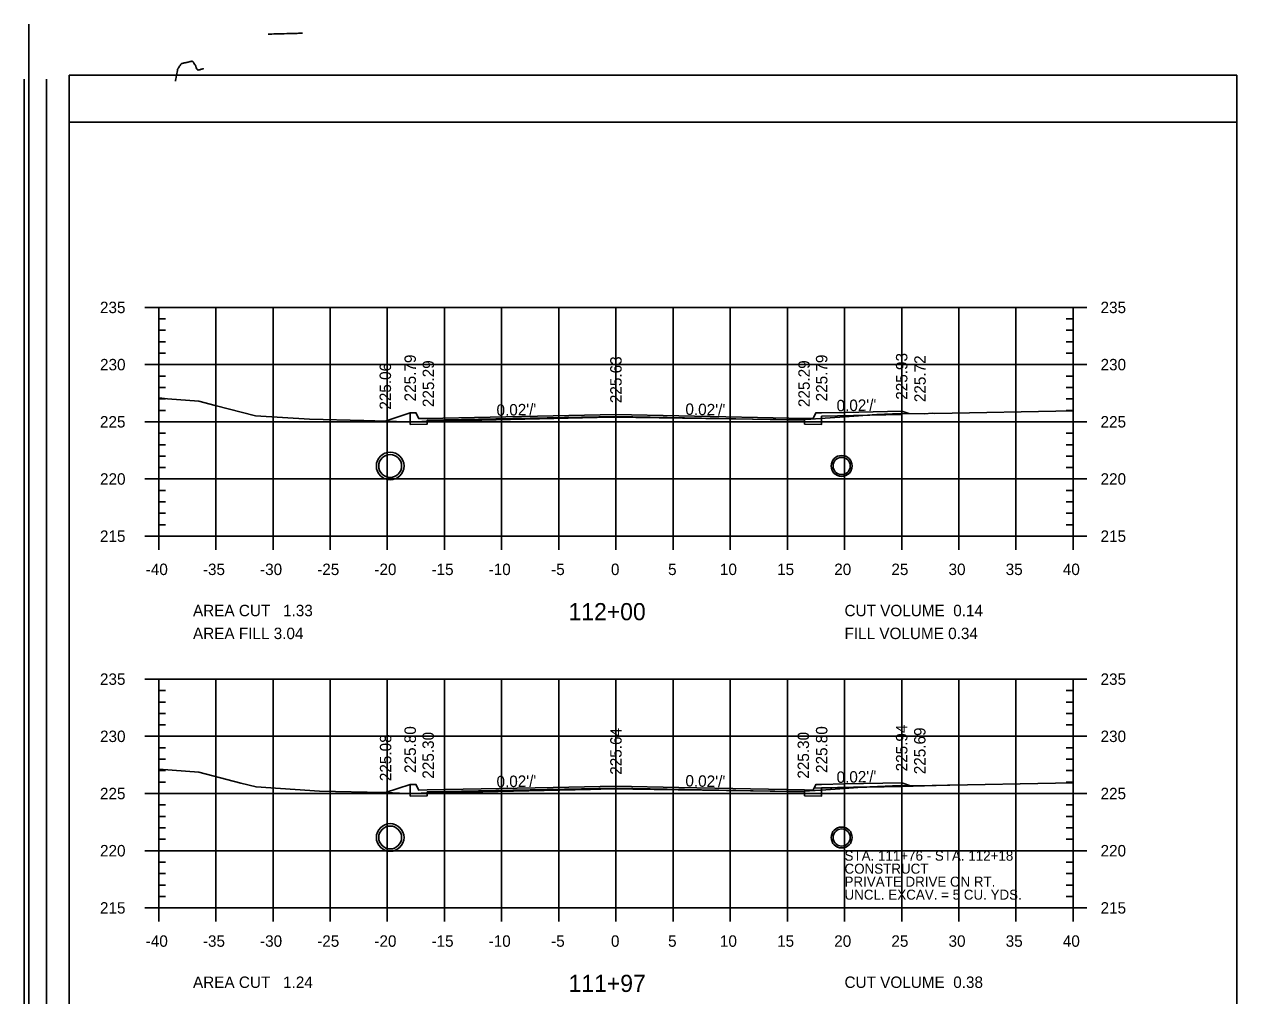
# Model space of a CAD drawing. Extents: x 1367903 to 1373764, y 376865 to 382130.
# Drawn here: x 1372830.3 to 1373042.4, y 377450.5 to 377620.4 of the extents above; entities that cross this region are included whole.
import ezdxf

# ---------------------------------------------------------------- set-up
doc = ezdxf.new("R2010")
doc.units = 0
for name, color, linetype in [('R_Axis', 7, 'Continuous'), ('R_Axis Annot', 7, 'Continuous'), ('R_Border', 7, 'Continuous'), ('R_Border PE', 7, 'Continuous'), ('R_Draft', 7, 'Continuous'), ('R_Drive', 7, 'Continuous'), ('R_Exist Surface', 7, 'Continuous'), ('R_Fin Surface', 7, 'Continuous'), ('R_Fin Surface Annot', 7, 'Continuous'), ('R_Grid', 7, 'Continuous'), ('R_Water', 7, 'Continuous')]:
    doc.layers.add(name, color=color, linetype=linetype)

msp = doc.modelspace()

# ---------------------------------------------------------------- linework, layer by layer
for points in [[(1372897.8, 377552.41), (1372897.8, 377551.74), (1372897.8, 377551.74), (1372897.8, 377550.38), (1372900.8, 377550.44), (1372900.8, 377551.11), (1372933.8, 377551.77), (1372966.8, 377551.11), (1372966.8, 377550.44), (1372969.8, 377550.38), (1372969.8, 377551.82), (1372983.8, 377552.1), (1372983.8, 377552.69)], [(1372897.8, 377487.43), (1372897.8, 377486.77), (1372897.8, 377486.77), (1372897.8, 377485.4), (1372900.8, 377485.46), (1372900.8, 377486.13), (1372933.8, 377486.79), (1372966.8, 377486.13), (1372966.8, 377485.46), (1372969.8, 377485.4), (1372969.8, 377486.85), (1372983.8, 377487.13), (1372983.8, 377487.71)]]:
    msp.add_lwpolyline(points)
at = {"layer": 'R_Axis'}
for p, q in [((1372851.4, 377570.84), (1372856.2, 377570.84)), ((1372853.8, 377530.84), (1372853.8, 377570.84)), ((1373016.2, 377570.84), (1373011.4, 377570.84)), ((1373013.8, 377530.84), (1373013.8, 377570.84)), ((1372853.8, 377568.84), (1372855, 377568.84)), ((1373013.8, 377568.84), (1373012.6, 377568.84)), ((1372853.8, 377566.84), (1372855, 377566.84)), ((1373013.8, 377566.84), (1373012.6, 377566.84)), ((1372853.8, 377564.84), (1372855, 377564.84)), ((1373013.8, 377564.84), (1373012.6, 377564.84)), ((1372853.8, 377562.84), (1372855, 377562.84)), ((1373013.8, 377562.84), (1373012.6, 377562.84)), ((1372851.4, 377560.84), (1372856.2, 377560.84)), ((1373016.2, 377560.84), (1373011.4, 377560.84)), ((1372853.8, 377558.84), (1372855, 377558.84)), ((1373013.8, 377558.84), (1373012.6, 377558.84)), ((1372853.8, 377556.84), (1372855, 377556.84)), ((1373013.8, 377556.84), (1373012.6, 377556.84)), ((1372853.8, 377554.84), (1372855, 377554.84)), ((1373013.8, 377554.84), (1373012.6, 377554.84)), ((1372853.8, 377552.84), (1372855, 377552.84)), ((1373013.8, 377552.84), (1373012.6, 377552.84)), ((1372851.4, 377550.84), (1372856.2, 377550.84)), ((1373016.2, 377550.84), (1373011.4, 377550.84)), ((1372853.8, 377548.84), (1372855, 377548.84)), ((1372853.8, 377546.84), (1372855, 377546.84)), ((1373013.8, 377548.84), (1373012.6, 377548.84)), ((1373013.8, 377546.84), (1373012.6, 377546.84)), ((1372853.8, 377544.84), (1372855, 377544.84)), ((1373013.8, 377544.84), (1373012.6, 377544.84)), ((1372853.8, 377542.84), (1372855, 377542.84)), ((1373013.8, 377542.84), (1373012.6, 377542.84)), ((1372851.4, 377540.84), (1372856.2, 377540.84)), ((1373016.2, 377540.84), (1373011.4, 377540.84)), ((1372853.8, 377538.84), (1372855, 377538.84)), ((1373013.8, 377538.84), (1373012.6, 377538.84)), ((1372853.8, 377536.84), (1372855, 377536.84)), ((1373013.8, 377536.84), (1373012.6, 377536.84)), ((1372853.8, 377534.84), (1372855, 377534.84)), ((1373013.8, 377534.84), (1373012.6, 377534.84)), ((1372853.8, 377528.44), (1372853.8, 377533.24)), ((1372853.8, 377532.84), (1372855, 377532.84)), ((1372863.8, 377528.44), (1372863.8, 377533.24)), ((1372873.8, 377528.44), (1372873.8, 377533.24)), ((1372883.8, 377528.44), (1372883.8, 377533.24)), ((1372893.8, 377528.44), (1372893.8, 377533.24)), ((1372903.8, 377528.44), (1372903.8, 377533.24)), ((1372913.8, 377528.44), (1372913.8, 377533.24)), ((1372923.8, 377528.44), (1372923.8, 377533.24)), ((1372933.8, 377528.44), (1372933.8, 377533.24)), ((1372943.8, 377528.44), (1372943.8, 377533.24)), ((1372953.8, 377528.44), (1372953.8, 377533.24)), ((1372963.8, 377528.44), (1372963.8, 377533.24)), ((1372973.8, 377528.44), (1372973.8, 377533.24)), ((1372983.8, 377528.44), (1372983.8, 377533.24)), ((1372993.8, 377528.44), (1372993.8, 377533.24)), ((1373003.8, 377528.44), (1373003.8, 377533.24)), ((1373013.8, 377532.84), (1373012.6, 377532.84)), ((1373013.8, 377528.44), (1373013.8, 377533.24)), ((1372851.4, 377530.84), (1372856.2, 377530.84)), ((1372853.8, 377530.84), (1373013.8, 377530.84)), ((1373016.2, 377530.84), (1373011.4, 377530.84)), ((1372851.4, 377505.84), (1372856.2, 377505.84)), ((1372853.8, 377465.84), (1372853.8, 377505.84)), ((1373016.2, 377505.84), (1373011.4, 377505.84)), ((1373013.8, 377465.84), (1373013.8, 377505.84)), ((1372853.8, 377503.84), (1372855, 377503.84)), ((1373013.8, 377503.84), (1373012.6, 377503.84)), ((1372853.8, 377501.84), (1372855, 377501.84)), ((1373013.8, 377501.84), (1373012.6, 377501.84)), ((1372853.8, 377499.84), (1372855, 377499.84)), ((1373013.8, 377499.84), (1373012.6, 377499.84)), ((1372853.8, 377497.84), (1372855, 377497.84)), ((1373013.8, 377497.84), (1373012.6, 377497.84)), ((1372851.4, 377495.84), (1372856.2, 377495.84)), ((1372853.8, 377493.84), (1372855, 377493.84)), ((1373016.2, 377495.84), (1373011.4, 377495.84)), ((1373013.8, 377493.84), (1373012.6, 377493.84)), ((1372853.8, 377491.84), (1372855, 377491.84)), ((1373013.8, 377491.84), (1373012.6, 377491.84)), ((1372853.8, 377489.84), (1372855, 377489.84)), ((1373013.8, 377489.84), (1373012.6, 377489.84)), ((1372853.8, 377487.84), (1372855, 377487.84)), ((1373013.8, 377487.84), (1373012.6, 377487.84)), ((1372851.4, 377485.84), (1372856.2, 377485.84)), ((1373016.2, 377485.84), (1373011.4, 377485.84)), ((1372853.8, 377483.84), (1372855, 377483.84)), ((1373013.8, 377483.84), (1373012.6, 377483.84)), ((1372853.8, 377481.84), (1372855, 377481.84)), ((1373013.8, 377481.84), (1373012.6, 377481.84)), ((1372853.8, 377479.84), (1372855, 377479.84)), ((1373013.8, 377479.84), (1373012.6, 377479.84)), ((1372853.8, 377477.84), (1372855, 377477.84)), ((1373013.8, 377477.84), (1373012.6, 377477.84)), ((1372851.4, 377475.84), (1372856.2, 377475.84)), ((1373016.2, 377475.84), (1373011.4, 377475.84)), ((1372853.8, 377473.84), (1372855, 377473.84)), ((1373013.8, 377473.84), (1373012.6, 377473.84)), ((1372853.8, 377471.84), (1372855, 377471.84)), ((1373013.8, 377471.84), (1373012.6, 377471.84)), ((1372853.8, 377469.84), (1372855, 377469.84)), ((1373013.8, 377469.84), (1373012.6, 377469.84)), ((1372853.8, 377463.44), (1372853.8, 377468.24)), ((1372853.8, 377467.84), (1372855, 377467.84)), ((1372863.8, 377463.44), (1372863.8, 377468.24)), ((1372873.8, 377463.44), (1372873.8, 377468.24)), ((1372883.8, 377463.44), (1372883.8, 377468.24)), ((1372893.8, 377463.44), (1372893.8, 377468.24)), ((1372903.8, 377463.44), (1372903.8, 377468.24)), ((1372913.8, 377463.44), (1372913.8, 377468.24)), ((1372923.8, 377463.44), (1372923.8, 377468.24)), ((1372933.8, 377463.44), (1372933.8, 377468.24)), ((1372943.8, 377463.44), (1372943.8, 377468.24)), ((1372953.8, 377463.44), (1372953.8, 377468.24)), ((1372963.8, 377463.44), (1372963.8, 377468.24)), ((1372973.8, 377463.44), (1372973.8, 377468.24)), ((1372983.8, 377463.44), (1372983.8, 377468.24)), ((1372993.8, 377463.44), (1372993.8, 377468.24)), ((1373003.8, 377463.44), (1373003.8, 377468.24)), ((1373013.8, 377467.84), (1373012.6, 377467.84)), ((1373013.8, 377463.44), (1373013.8, 377468.24)), ((1372851.4, 377465.84), (1372856.2, 377465.84)), ((1372853.8, 377465.84), (1373013.8, 377465.84)), ((1373016.2, 377465.84), (1373011.4, 377465.84))]:
    msp.add_line(p, q, dxfattribs=at)
at = {"layer": 'R_Border'}
for p, q in [((1372831.08, 377620.35), (1372831.08, 377279.12)), ((1372838.11, 377611.47), (1373042.43, 377611.47)), ((1372838.11, 377611.47), (1372838.11, 377280.59)), ((1373042.43, 377280.59), (1373042.43, 377611.47))]:
    msp.add_line(p, q, dxfattribs=at)
at = {"layer": 'R_Border PE'}
for p, q in [((1372830.27, 377610.76), (1372830.27, 377288.8)), ((1372834.19, 377610.76), (1372834.19, 377288.8)), ((1372838.11, 377603.25), (1373042.43, 377603.25)), ((1372838.11, 377288.8), (1372838.11, 377603.25)), ((1373042.43, 377603.25), (1373042.43, 377288.8))]:
    msp.add_line(p, q, dxfattribs=at)
for points in [[(1372874.97, 377618.69), (1372874.91, 377618.69), (1372874.63, 377618.68), (1372874.5, 377618.68), (1372874.43, 377618.67), (1372874.28, 377618.67), (1372873.92, 377618.66), (1372873.59, 377618.65), (1372872.96, 377618.63)], [(1372875.42, 377618.7), (1372874.97, 377618.69)], [(1372878.98, 377618.79), (1372878.63, 377618.78), (1372878.43, 377618.78), (1372878.27, 377618.77), (1372878.05, 377618.76), (1372877.89, 377618.76), (1372877.69, 377618.75), (1372877.45, 377618.75), (1372877.26, 377618.74), (1372876.97, 377618.73), (1372876.88, 377618.73), (1372876.82, 377618.73), (1372876.61, 377618.72), (1372876.5, 377618.72), (1372876.28, 377618.71), (1372876.2, 377618.72), (1372875.77, 377618.7), (1372875.53, 377618.7), (1372875.42, 377618.7)], [(1372861.66, 377612.54), (1372861.65, 377612.55), (1372861.62, 377612.55), (1372861.6, 377612.55), (1372861.58, 377612.55), (1372861.55, 377612.55), (1372861.53, 377612.55), (1372861.5, 377612.55), (1372861.36, 377612.51), (1372861.24, 377612.48), (1372860.97, 377612.41), (1372860.76, 377612.36), (1372860.73, 377612.35), (1372860.71, 377612.35), (1372860.69, 377612.34), (1372860.68, 377612.34), (1372860.67, 377612.35), (1372860.65, 377612.35), (1372860.62, 377612.36), (1372860.6, 377612.38), (1372860.58, 377612.39), (1372860.56, 377612.4), (1372860.54, 377612.42), (1372860.53, 377612.45), (1372860.51, 377612.47), (1372860.5, 377612.5), (1372860.48, 377612.55), (1372860.38, 377612.76), (1372860.27, 377613), (1372860.16, 377613.23), (1372860.15, 377613.26), (1372860.14, 377613.28), (1372860.1, 377613.34), (1372860.07, 377613.39), (1372859.95, 377613.57), (1372859.87, 377613.69), (1372859.84, 377613.74), (1372859.83, 377613.76), (1372859.81, 377613.78), (1372859.79, 377613.81), (1372859.77, 377613.83), (1372859.76, 377613.84), (1372859.74, 377613.85), (1372859.72, 377613.87), (1372859.71, 377613.87), (1372859.67, 377613.88), (1372859.65, 377613.88), (1372859.63, 377613.88), (1372859.59, 377613.88), (1372859.49, 377613.86), (1372859.32, 377613.82), (1372859.12, 377613.77), (1372858.98, 377613.74), (1372858.87, 377613.72), (1372858.73, 377613.69), (1372858.62, 377613.66), (1372858.44, 377613.63), (1372858.22, 377613.58), (1372858.17, 377613.57), (1372858.05, 377613.54), (1372857.93, 377613.52), (1372857.89, 377613.51), (1372857.86, 377613.5), (1372857.84, 377613.5), (1372857.83, 377613.49), (1372857.82, 377613.49), (1372857.8, 377613.47), (1372857.77, 377613.46), (1372857.75, 377613.44), (1372857.73, 377613.42), (1372857.7, 377613.39), (1372857.67, 377613.35), (1372857.64, 377613.31), (1372857.61, 377613.26), (1372857.54, 377613.16), (1372857.45, 377613.02), (1372857.37, 377612.89), (1372857.27, 377612.75), (1372857.22, 377612.67), (1372857.19, 377612.62), (1372857.15, 377612.55), (1372857.14, 377612.54), (1372857.13, 377612.52), (1372857.12, 377612.5), (1372857.11, 377612.48), (1372857.11, 377612.46), (1372857.1, 377612.44), (1372857.09, 377612.42), (1372857.09, 377612.39), (1372857.08, 377612.37), (1372857.08, 377612.35), (1372857.08, 377612.33), (1372857.06, 377612.24), (1372857.02, 377612), (1372856.97, 377611.76), (1372856.95, 377611.65), (1372856.87, 377611.18), (1372856.84, 377611.04), (1372856.8, 377610.84), (1372856.75, 377610.54), (1372856.72, 377610.39)]]:
    msp.add_lwpolyline(points, dxfattribs=at)
at = {"layer": 'R_Drive'}
for q in [(1372968.47, 377486.77), (1372993.8, 377487.34)]:
    msp.add_line((1372983.8, 377487.08), q, dxfattribs=at)
at = {"layer": 'R_Exist Surface'}
for points in [[(1372853.8, 377555.01), (1372855.33, 377554.87), (1372860.84, 377554.43), (1372863.67, 377553.69), (1372870.73, 377551.9), (1372880.19, 377551.29), (1372889.7, 377551.08), (1372893.58, 377550.95), (1372893.93, 377550.94), (1372896.92, 377550.83), (1372902.73, 377550.97), (1372933.04, 377551.62), (1372933.21, 377551.62), (1372965.87, 377551.18), (1372967.93, 377551.31), (1372973.77, 377551.71), (1372979.43, 377552.12), (1372983.54, 377552.28), (1372987.71, 377552.25), (1372989.19, 377552.34), (1372989.62, 377552.29), (1373013.8, 377552.73)], [(1372853.8, 377490.12), (1372860.84, 377489.57), (1372868.15, 377487.66), (1372870.85, 377486.98), (1372881.94, 377486.26), (1372893.1, 377486.01), (1372893.43, 377486), (1372893.46, 377486), (1372895.91, 377485.91), (1372896.54, 377485.87), (1372896.9, 377485.87), (1372897.03, 377485.87), (1372929.35, 377486.55), (1372933.05, 377486.65), (1372940.51, 377486.55), (1372965.8, 377486.22), (1372970.55, 377486.5), (1372973.8, 377486.73), (1372976.95, 377486.95), (1372983.55, 377487.22), (1372987.32, 377487.19), (1372989.16, 377487.26), (1373013.8, 377487.71)]]:
    msp.add_lwpolyline(points, dxfattribs=at)
at = {"layer": 'R_Fin Surface'}
for points in [[(1372893.45, 377550.96), (1372897.8, 377552.41), (1372898.8, 377552.41), (1372899.3, 377551.41), (1372900.8, 377551.44), (1372922.8, 377551.88), (1372933.8, 377552.1), (1372944.8, 377551.88), (1372966.8, 377551.44), (1372968.3, 377551.41), (1372968.8, 377552.41), (1372969.8, 377552.41), (1372973.8, 377552.49), (1372983.8, 377552.69), (1372985.05, 377552.27)], [(1372893.5, 377486), (1372897.8, 377487.43), (1372898.8, 377487.43), (1372899.3, 377486.43), (1372900.8, 377486.46), (1372922.8, 377486.9), (1372933.8, 377487.12), (1372944.8, 377486.9), (1372966.8, 377486.46), (1372968.3, 377486.43), (1372968.8, 377487.43), (1372969.8, 377487.43), (1372973.8, 377487.51), (1372983.8, 377487.71), (1372985.32, 377487.21)]]:
    msp.add_lwpolyline(points, dxfattribs=at)
at = {"layer": 'R_Grid'}
for p, q in [((1372853.8, 377570.84), (1373013.8, 377570.84)), ((1372853.8, 377530.84), (1372853.8, 377570.84)), ((1372863.8, 377530.84), (1372863.8, 377570.84)), ((1372873.8, 377530.84), (1372873.8, 377570.84)), ((1372883.8, 377530.84), (1372883.8, 377570.84)), ((1372893.8, 377530.84), (1372893.8, 377570.84)), ((1372903.8, 377530.84), (1372903.8, 377570.84)), ((1372913.8, 377530.84), (1372913.8, 377570.84)), ((1372923.8, 377530.84), (1372923.8, 377570.84)), ((1372933.8, 377530.84), (1372933.8, 377570.84)), ((1372943.8, 377530.84), (1372943.8, 377570.84)), ((1372953.8, 377530.84), (1372953.8, 377570.84)), ((1372963.8, 377530.84), (1372963.8, 377570.84)), ((1372973.8, 377530.84), (1372973.8, 377570.84)), ((1372983.8, 377530.84), (1372983.8, 377570.84)), ((1372993.8, 377530.84), (1372993.8, 377570.84)), ((1373003.8, 377530.84), (1373003.8, 377570.84)), ((1373013.8, 377530.84), (1373013.8, 377570.84)), ((1372853.8, 377560.84), (1373013.8, 377560.84)), ((1372853.8, 377550.84), (1373013.8, 377550.84)), ((1372853.8, 377540.84), (1373013.8, 377540.84)), ((1372853.8, 377530.84), (1373013.8, 377530.84)), ((1372853.8, 377505.84), (1373013.8, 377505.84)), ((1372853.8, 377465.84), (1372853.8, 377505.84)), ((1372863.8, 377465.84), (1372863.8, 377505.84)), ((1372873.8, 377465.84), (1372873.8, 377505.84)), ((1372883.8, 377465.84), (1372883.8, 377505.84)), ((1372893.8, 377465.84), (1372893.8, 377505.84)), ((1372903.8, 377465.84), (1372903.8, 377505.84)), ((1372913.8, 377465.84), (1372913.8, 377505.84)), ((1372923.8, 377465.84), (1372923.8, 377505.84)), ((1372933.8, 377465.84), (1372933.8, 377505.84)), ((1372943.8, 377465.84), (1372943.8, 377505.84)), ((1372953.8, 377465.84), (1372953.8, 377505.84)), ((1372963.8, 377465.84), (1372963.8, 377505.84)), ((1372973.8, 377465.84), (1372973.8, 377505.84)), ((1372983.8, 377465.84), (1372983.8, 377505.84)), ((1372993.8, 377465.84), (1372993.8, 377505.84)), ((1373003.8, 377465.84), (1373003.8, 377505.84)), ((1373013.8, 377465.84), (1373013.8, 377505.84)), ((1372853.8, 377495.84), (1373013.8, 377495.84)), ((1372853.8, 377485.84), (1373013.8, 377485.84)), ((1372853.8, 377475.84), (1373013.8, 377475.84)), ((1372853.8, 377465.84), (1373013.8, 377465.84))]:
    msp.add_line(p, q, dxfattribs=at)
at = {"layer": 'R_Water'}
for p, q in [((1372894.3, 377545.56), (1372894.3, 377545.51)), ((1372894.3, 377545.14), (1372894.3, 377545.09)), ((1372973.3, 377544.97), (1372973.3, 377544.93)), ((1372973.3, 377544.64), (1372973.3, 377544.59)), ((1372894.3, 377541.14), (1372894.3, 377541.09)), ((1372894.3, 377540.72), (1372894.3, 377540.67)), ((1372973.3, 377541.64), (1372973.3, 377541.59)), ((1372973.3, 377541.31), (1372973.3, 377541.26)), ((1372894.3, 377480.59), (1372894.3, 377480.54)), ((1372894.3, 377480.18), (1372894.3, 377480.13)), ((1372973.3, 377480.01), (1372973.3, 377479.96)), ((1372973.3, 377479.68), (1372973.3, 377479.63)), ((1372894.3, 377476.18), (1372894.3, 377476.13)), ((1372894.3, 377475.76), (1372894.3, 377475.71)), ((1372973.3, 377476.68), (1372973.3, 377476.63)), ((1372973.3, 377476.34), (1372973.3, 377476.3))]:
    msp.add_line(p, q, dxfattribs=at)
for centre, radius in [((1372894.3, 377543.11), 2.42), ((1372894.3, 377543.11), 2), ((1372973.3, 377543.12), 1.83), ((1372973.3, 377543.12), 1.5), ((1372894.3, 377478.15), 2.42), ((1372894.3, 377478.15), 2), ((1372973.3, 377478.15), 1.83), ((1372973.3, 377478.15), 1.5)]:
    msp.add_circle(centre, radius, dxfattribs=at)

# ---------------------------------------------------------------- texts
at = {"layer": 'R_Axis Annot'}
for s, height, p in [('235', 2, (1372843.52, 377569.84)), ('235', 2, (1373018.6, 377569.84)), ('230', 2, (1372843.53, 377559.84)), ('230', 2, (1373018.6, 377559.84)), ('225', 2, (1372843.52, 377549.84)), ('225', 2, (1373018.6, 377549.84)), ('220', 2, (1372843.53, 377539.84)), ('220', 2, (1373018.6, 377539.84)), ('215', 2, (1372843.52, 377529.84)), ('215', 2, (1373018.6, 377529.84)), ('-40', 2, (1372851.53, 377524.04)), ('-35', 2, (1372861.53, 377524.04)), ('-30', 2, (1372871.53, 377524.04)), ('-25', 2, (1372881.53, 377524.04)), ('-20', 2, (1372891.53, 377524.04)), ('-15', 2, (1372901.53, 377524.04)), ('-10', 2, (1372911.53, 377524.04)), ('-5', 2, (1372922.46, 377524.04)), ('0', 2, (1372932.93, 377524.04)), ('5', 2, (1372942.93, 377524.04)), ('10', 2, (1372952, 377524.04)), ('15', 2, (1372962, 377524.04)), ('20', 2, (1372972, 377524.04)), ('25', 2, (1372982, 377524.04)), ('30', 2, (1372992, 377524.04)), ('35', 2, (1373002, 377524.04)), ('40', 2, (1373012, 377524.04)), ('AREA CUT   1.33', 2, (1372859.8, 377516.84)), ('112+00', 3, (1372925.51, 377516.14)), ('CUT VOLUME  0.14', 2, (1372973.8, 377516.84)), ('AREA FILL 3.04', 2, (1372859.8, 377512.84)), ('FILL VOLUME 0.34', 2, (1372973.8, 377512.84)), ('235', 2, (1372843.52, 377504.84)), ('235', 2, (1373018.6, 377504.84)), ('230', 2, (1372843.53, 377494.84)), ('230', 2, (1373018.6, 377494.84)), ('225', 2, (1372843.52, 377484.84)), ('225', 2, (1373018.6, 377484.84)), ('220', 2, (1372843.53, 377474.84)), ('220', 2, (1373018.6, 377474.84)), ('215', 2, (1372843.52, 377464.84)), ('215', 2, (1373018.6, 377464.84)), ('-40', 2, (1372851.53, 377459.04)), ('-35', 2, (1372861.53, 377459.04)), ('-30', 2, (1372871.53, 377459.04)), ('-25', 2, (1372881.53, 377459.04)), ('-20', 2, (1372891.53, 377459.04)), ('-15', 2, (1372901.53, 377459.04)), ('-10', 2, (1372911.53, 377459.04)), ('-5', 2, (1372922.46, 377459.04)), ('0', 2, (1372932.93, 377459.04)), ('5', 2, (1372942.93, 377459.04)), ('10', 2, (1372952, 377459.04)), ('15', 2, (1372962, 377459.04)), ('20', 2, (1372972, 377459.04)), ('25', 2, (1372982, 377459.04)), ('30', 2, (1372992, 377459.04)), ('35', 2, (1373002, 377459.04)), ('40', 2, (1373012, 377459.04)), ('AREA CUT   1.24', 2, (1372859.8, 377451.84)), ('111+97', 3, (1372925.52, 377451.14)), ('CUT VOLUME  0.38', 2, (1372973.8, 377451.84))]:
    msp.add_text(s, height=height, dxfattribs=at).set_placement(p)
at = {"layer": 'R_Draft'}
for s, p in [('STA. 111+76 - STA. 112+18', (1372973.8, 377474.09)), ('CONSTRUCT', (1372973.8, 377471.82)), ('PRIVATE DRIVE ON RT.', (1372973.8, 377469.55)), ('UNCL. EXCAV. = 5 CU. YDS.', (1372973.8, 377467.28))]:
    msp.add_text(s, height=1.75, dxfattribs=at).set_placement(p)
at = {"layer": 'R_Fin Surface Annot'}
for s, rotation, p in [('225.79', 90, (1372898.8, 377554.41)), ('225.63', 90, (1372934.8, 377554.1)), ('225.79', 90, (1372970.8, 377554.41)), ('225.93', 90, (1372984.8, 377554.69)), ('225.72', 90, (1372988.01, 377554.27)), ('225.06', 90, (1372894.45, 377552.96)), ('225.29', 90, (1372901.98, 377553.41)), ('225.29', 90, (1372967.72, 377553.41)), ("0.02'/'", 1.1458, (1372912.93, 377551.88)), ("0.02'/'", 358.8542, (1372945.94, 377552.06)), ("0.02'/'", 1.1458, (1372972.43, 377552.66)), ('225.08', 90, (1372894.5, 377488)), ('225.80', 90, (1372898.8, 377489.43)), ('225.30', 90, (1372901.95, 377488.43)), ('225.64', 90, (1372934.8, 377489.12)), ('225.30', 90, (1372967.59, 377488.43)), ('225.80', 90, (1372970.8, 377489.43)), ('225.94', 90, (1372984.8, 377489.71)), ('225.69', 90, (1372987.97, 377489.21)), ("0.02'/'", 1.1458, (1372972.43, 377487.69)), ("0.02'/'", 1.1458, (1372912.93, 377486.91)), ("0.02'/'", 358.8542, (1372945.94, 377487.08))]:
    msp.add_text(s, height=2, rotation=rotation, dxfattribs=at).set_placement(p)

doc.saveas('drawing.dxf')
